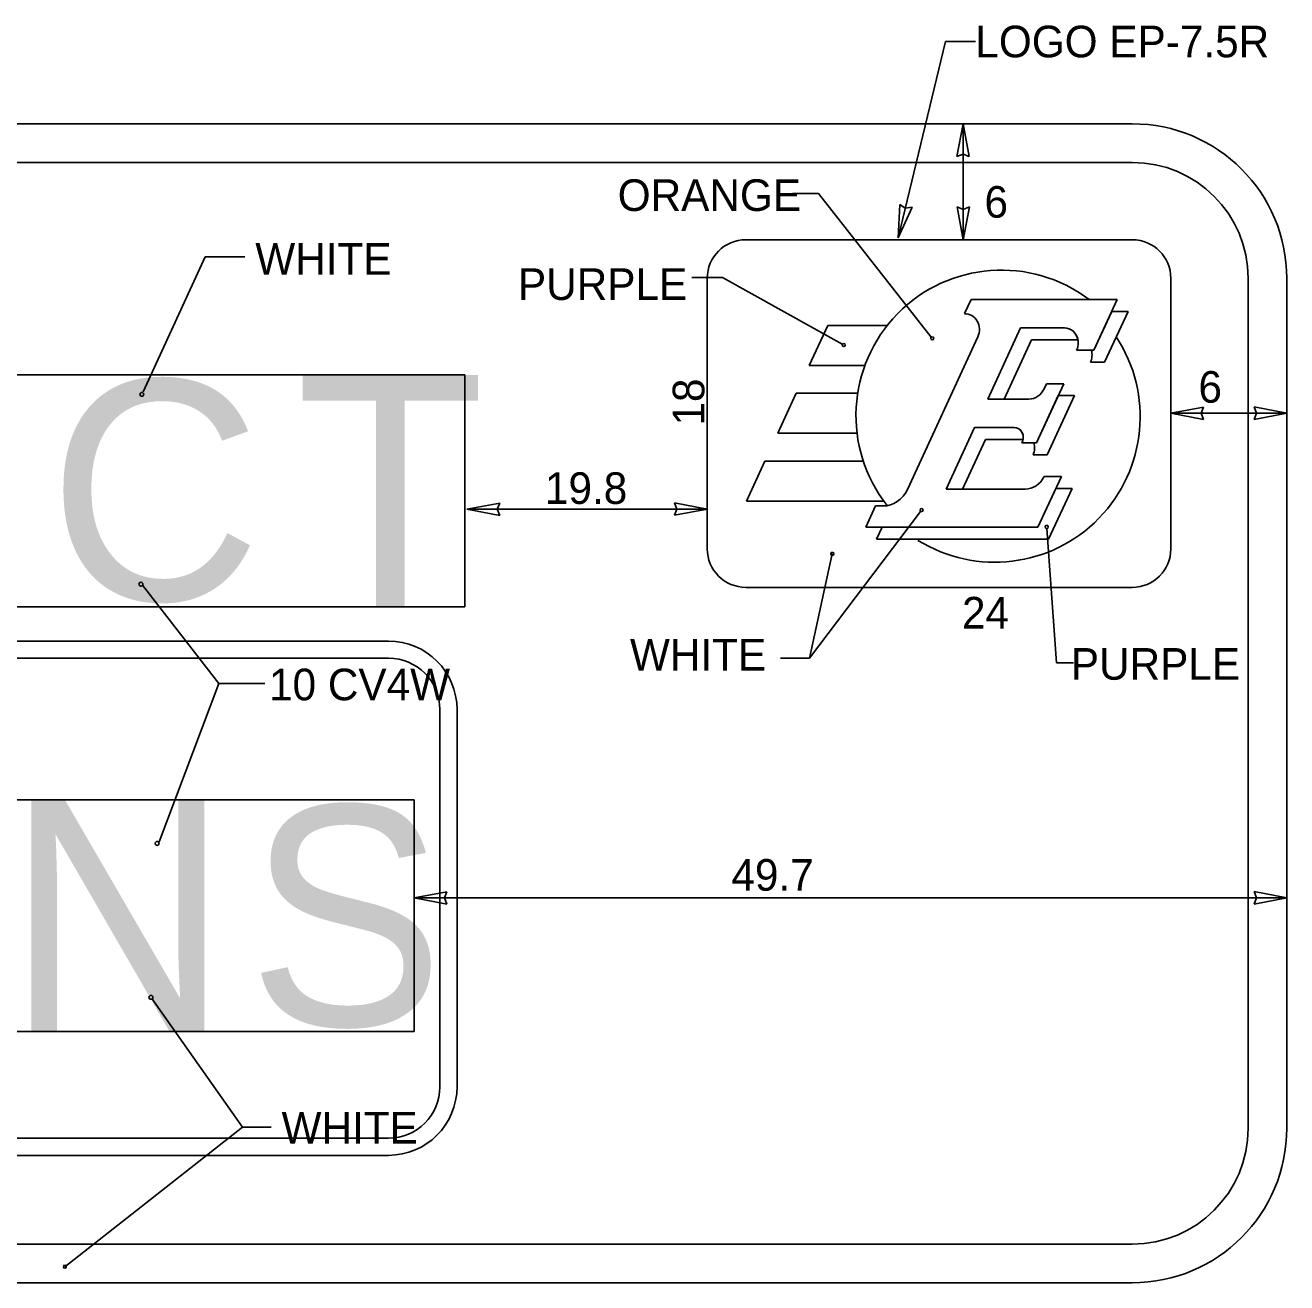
# Model space of a CAD drawing. Extents: x 319706 to 320346, y 1621790 to 1622121.
# Drawn here: x 319787.7 to 319843.5, y 1622064.8 to 1622120.5 of the extents above; entities that cross this region are included whole.
import ezdxf

# ---------------------------------------------------------------- set-up
doc = ezdxf.new("R2010")
doc.units = 0
for name, color, linetype in [('1', 7, 'Continuous'), ('52', 7, 'Continuous'), ('GSOutline', 7, 'Continuous'), ('SignPanel', 7, 'Continuous'), ('SOILS_SP83_SHP', 7, 'Continuous')]:
    doc.layers.add(name, color=color, linetype=linetype)

msp = doc.modelspace()

# ---------------------------------------------------------------- linework, layer by layer
at = {"layer": '1'}
for p, q in [((319826.341, 1622111.1), (319828.431, 1622119.783)), ((319828.431, 1622119.783), (319829.754, 1622119.783)), ((319829.217, 1622111.012), (319829.217, 1622116.142)), ((319821.667, 1622113.057), (319822.816, 1622113.057)), ((319822.816, 1622113.057), (319827.798, 1622106.695)), ((319795.671, 1622110.252), (319792.921, 1622104.281)), ((319797.422, 1622110.252), (319795.671, 1622110.252)), ((319817.21, 1622109.331), (319818.56, 1622109.331)), ((319818.56, 1622109.331), (319823.895, 1622106.373)), ((319838.407, 1622103.329), (319843.537, 1622103.329)), ((319822.411, 1622092.485), (319827.326, 1622098.98)), ((319833.339, 1622092.275), (319832.92, 1622098.223)), ((319822.411, 1622092.485), (319823.424, 1622097.107)), ((319796.271, 1622091.368), (319792.887, 1622095.721)), ((319821.127, 1622092.485), (319822.411, 1622092.485)), ((319834.105, 1622092.275), (319833.339, 1622092.275)), ((319796.271, 1622091.368), (319793.625, 1622084.362)), ((319798.305, 1622091.368), (319796.271, 1622091.368)), ((319804.916, 1622081.875), (319843.537, 1622081.875)), ((319797.321, 1622071.725), (319793.301, 1622077.427)), ((319797.321, 1622071.725), (319789.454, 1622065.552)), ((319798.58, 1622071.725), (319797.321, 1622071.725))]:
    msp.add_line(p, q, dxfattribs=at)
for centre, major_axis, ratio in [((319823.928, 1622106.348), (0, 0.0707), 0.906668), ((319827.845, 1622106.646), (0, 0.0707), 0.906668), ((319792.863, 1622104.164), (0.0872, 0), 0.980296), ((319827.373, 1622099.044), (0, 0.0707), 0.906668), ((319832.911, 1622098.299), (0, 0.0707), 0.906668), ((319823.423, 1622097.106), (0, 0.0707), 0.906668), ((319792.822, 1622095.763), (0.0872, 0), 0.980296), ((319793.54, 1622084.287), (0.0881, 0), 0.97059), ((319793.267, 1622077.473), (0.0881, 0), 0.97059), ((319789.453, 1622065.552), (0, 0.0707), 0.906668)]:
    msp.add_ellipse(centre, major_axis=major_axis, ratio=ratio, dxfattribs=at)
at = {"layer": '52'}
for p, q in [((319829.217, 1622116.142), (319828.937, 1622114.692)), ((319829.487, 1622114.692), (319829.217, 1622116.142)), ((319828.937, 1622114.692), (319829.217, 1622114.802)), ((319829.217, 1622114.802), (319829.487, 1622114.692)), ((319826.418, 1622112.573), (319826.341, 1622111.1)), ((319826.654, 1622112.403), (319826.418, 1622112.573)), ((319826.341, 1622111.1), (319826.952, 1622112.445)), ((319826.952, 1622112.445), (319826.654, 1622112.403)), ((319829.217, 1622112.352), (319828.947, 1622112.462)), ((319828.947, 1622112.462), (319829.217, 1622111.012)), ((319829.217, 1622111.012), (319829.497, 1622112.462)), ((319829.497, 1622112.462), (319829.217, 1622112.352)), ((319843.537, 1622103.329), (319842.087, 1622103.609)), ((319842.087, 1622103.609), (319842.197, 1622103.329)), ((319839.857, 1622103.599), (319838.407, 1622103.329)), ((319838.407, 1622103.329), (319839.857, 1622103.049)), ((319839.747, 1622103.329), (319839.857, 1622103.599)), ((319839.857, 1622103.049), (319839.747, 1622103.329)), ((319842.197, 1622103.329), (319842.087, 1622103.059)), ((319842.087, 1622103.059), (319843.537, 1622103.329)), ((319808.702, 1622099.355), (319807.252, 1622099.085)), ((319808.592, 1622099.085), (319808.702, 1622099.355)), ((319817.887, 1622099.085), (319816.437, 1622099.365)), ((319816.437, 1622099.365), (319816.547, 1622099.085)), ((319807.252, 1622099.085), (319808.702, 1622098.805)), ((319808.702, 1622098.805), (319808.592, 1622099.085)), ((319816.547, 1622099.085), (319816.437, 1622098.815)), ((319816.437, 1622098.815), (319817.887, 1622099.085)), ((319806.366, 1622082.145), (319804.916, 1622081.875)), ((319804.916, 1622081.875), (319806.366, 1622081.595)), ((319806.256, 1622081.875), (319806.366, 1622082.145)), ((319806.366, 1622081.595), (319806.256, 1622081.875)), ((319843.537, 1622081.875), (319842.087, 1622082.155)), ((319842.087, 1622082.155), (319842.197, 1622081.875)), ((319842.197, 1622081.875), (319842.087, 1622081.605)), ((319842.087, 1622081.605), (319843.537, 1622081.875))]:
    msp.add_line(p, q, dxfattribs=at)
at = {"layer": 'GSOutline'}
for p, q in [((319803.779, 1622093.246), (319755.212, 1622093.246)), ((319803.779, 1622092.488), (319755.212, 1622092.488)), ((319806.055, 1622073.516), (319806.055, 1622090.211)), ((319806.814, 1622073.516), (319806.814, 1622090.211)), ((319755.212, 1622071.24), (319803.779, 1622071.24)), ((319755.212, 1622070.481), (319803.779, 1622070.481))]:
    msp.add_line(p, q, dxfattribs=at)
for centre, radius, start, end in [((319803.779, 1622090.211), 3.035, 0, 90), ((319803.779, 1622090.211), 2.277, 0, 90), ((319803.779, 1622073.516), 3.035, 270, 0), ((319803.779, 1622073.516), 2.277, 270, 0)]:
    msp.add_arc(centre, radius, start, end, dxfattribs=at)
at = {"layer": 'SignPanel'}
for p, q in [((319727.257, 1622116.142), (319836.697, 1622116.142)), ((319727.257, 1622114.432), (319836.697, 1622114.432)), ((319819.597, 1622111.012), (319836.697, 1622111.012)), ((319817.887, 1622097.332), (319817.887, 1622109.302)), ((319838.407, 1622097.332), (319838.407, 1622109.302)), ((319841.827, 1622071.682), (319841.827, 1622109.302)), ((319843.537, 1622071.682), (319843.537, 1622109.302)), ((319829.565, 1622108.368), (319829.274, 1622107.738)), ((319829.565, 1622108.368), (319836.037, 1622108.368)), ((319836.037, 1622108.368), (319835, 1622106.123)), ((319835, 1622106.123), (319835.792, 1622107.837)), ((319836.511, 1622107.837), (319835.474, 1622105.592)), ((319836.511, 1622107.837), (319835.474, 1622105.592)), ((319835.792, 1622107.837), (319836.511, 1622107.837)), ((319835.792, 1622107.837), (319836.511, 1622107.837)), ((319823.219, 1622107.217), (319822.402, 1622105.449)), ((319825.858, 1622107.217), (319823.219, 1622107.217)), ((319831.757, 1622107.108), (319830.303, 1622103.959)), ((319831.757, 1622107.108), (319830.303, 1622103.959)), ((319833.699, 1622107.108), (319831.757, 1622107.108)), ((319833.699, 1622107.108), (319831.757, 1622107.108)), ((319826.746, 1622099.958), (319829.864, 1622106.709)), ((319832.232, 1622106.577), (319831.022, 1622103.959)), ((319831.022, 1622103.959), (319832.232, 1622106.577)), ((319834.294, 1622106.577), (319832.232, 1622106.577)), ((319832.232, 1622106.577), (319834.294, 1622106.577)), ((319835, 1622106.123), (319834.238, 1622106.123)), ((319834.886, 1622106.123), (319835, 1622106.123)), ((319824.868, 1622105.449), (319822.402, 1622105.449)), ((319834.849, 1622105.592), (319835.474, 1622105.592)), ((319835.474, 1622105.592), (319834.849, 1622105.592)), ((319821.83, 1622104.212), (319821.013, 1622102.444)), ((319824.548, 1622104.212), (319821.83, 1622104.212)), ((319833.667, 1622104.638), (319832.457, 1622102.018)), ((319832.905, 1622104.638), (319832.803, 1622104.416)), ((319832.905, 1622104.638), (319833.667, 1622104.638)), ((319830.303, 1622103.959), (319832.124, 1622103.959)), ((319830.303, 1622103.959), (319831.022, 1622103.959)), ((319832.457, 1622102.018), (319833.422, 1622104.108)), ((319834.141, 1622104.108), (319832.932, 1622101.488)), ((319834.141, 1622104.108), (319832.932, 1622101.488)), ((319833.422, 1622104.108), (319834.141, 1622104.108)), ((319833.422, 1622104.108), (319834.141, 1622104.108)), ((319829.72, 1622102.698), (319828.46, 1622099.969)), ((319829.72, 1622102.698), (319828.46, 1622099.969)), ((319831.476, 1622102.698), (319829.72, 1622102.698)), ((319831.476, 1622102.698), (319829.72, 1622102.698)), ((319824.52, 1622102.444), (319821.013, 1622102.444)), ((319830.197, 1622102.168), (319829.18, 1622099.969)), ((319829.18, 1622099.969), (319830.197, 1622102.168)), ((319831.869, 1622102.168), (319830.197, 1622102.168)), ((319830.197, 1622102.168), (319831.869, 1622102.168)), ((319831.814, 1622102.018), (319832.457, 1622102.018)), ((319832.344, 1622102.018), (319832.457, 1622102.018)), ((319832.932, 1622101.488), (319832.306, 1622101.488)), ((319832.932, 1622101.488), (319832.306, 1622101.488)), ((319820.441, 1622101.205), (319819.624, 1622099.438)), ((319824.797, 1622101.205), (319820.441, 1622101.205)), ((319833.561, 1622100.535), (319832.523, 1622098.289)), ((319832.798, 1622100.535), (319833.561, 1622100.535)), ((319828.46, 1622099.969), (319831.954, 1622099.969)), ((319828.46, 1622099.969), (319828.46, 1622099.969)), ((319828.46, 1622099.969), (319829.18, 1622099.969)), ((319832.523, 1622098.289), (319833.315, 1622100.004)), ((319834.035, 1622100.004), (319832.998, 1622097.758)), ((319834.035, 1622100.004), (319832.998, 1622097.758)), ((319833.315, 1622100.004), (319834.035, 1622100.004)), ((319833.315, 1622100.004), (319834.035, 1622100.004)), ((319819.624, 1622099.438), (319825.705, 1622099.438)), ((319824.909, 1622098.289), (319825.341, 1622099.225)), ((319825.341, 1622099.225), (319825.661, 1622099.225)), ((319807.252, 1622099.085), (319817.887, 1622099.085)), ((319832.523, 1622098.289), (319824.909, 1622098.289)), ((319825.383, 1622097.758), (319825.628, 1622098.289)), ((319825.383, 1622097.758), (319825.628, 1622098.289)), ((319825.628, 1622098.289), (319832.523, 1622098.289)), ((319832.998, 1622097.758), (319825.383, 1622097.758)), ((319832.998, 1622097.758), (319825.383, 1622097.758)), ((319819.597, 1622095.622), (319836.697, 1622095.622)), ((319726.616, 1622066.552), (319836.697, 1622066.552)), ((319727.257, 1622064.842), (319836.697, 1622064.842))]:
    msp.add_line(p, q, dxfattribs=at)
for centre, radius, start, end in [((319836.697, 1622109.301), 6.84, 0, 90), ((319836.697, 1622109.301), 5.13, 0, 90), ((319819.597, 1622109.301), 1.71, 90, 180), ((319836.697, 1622109.301), 1.71, 0, 90), ((319830.91, 1622103.226), 6.439, 52.9547, 218.1763), ((319830.61, 1622103.173), 6.439, 238.1578, 33.3171), ((319819.597, 1622097.331), 1.71, 180, 270), ((319836.697, 1622097.331), 1.71, 270, 360), ((319836.697, 1622071.681), 5.13, 270, 0), ((319836.697, 1622071.681), 6.84, 270, 0)]:
    msp.add_arc(centre, radius, start, end, dxfattribs=at)
for centre, major_axis, start_param, end_param in [((319829.292, 1622107.029), (0, 0.707), 4.241328, 6.314398), ((319833.698, 1622106.435), (0, 0.672), 4.227342, 6.283185), ((319833.698, 1622106.435), (0, 0.672), 4.924772, 6.283185), ((319834.309, 1622105.904), (0, 0.672), 4.227342, 5.041732), ((319834.309, 1622105.904), (0, 0.672), 4.227342, 5.041732), ((319832.124, 1622104.797), (0, 0.84), 3.141593, 4.241405), ((319831.475, 1622102.255), (0, 0.442), 4.144801, 6.283185), ((319831.475, 1622102.255), (0, 0.442), 4.511031, 6.283185), ((319831.767, 1622101.8), (0, 0.672), 4.227342, 5.041732), ((319831.767, 1622101.8), (0, 0.672), 4.227342, 5.041732), ((319831.954, 1622101.018), (0, 1.05), 3.141593, 4.232591), ((319825.66, 1622100.568), (0, 1.344), 3.141593, 4.241135)]:
    msp.add_ellipse(centre, major_axis=major_axis, ratio=0.906668, start_param=start_param, end_param=end_param, dxfattribs=at)
at = {"layer": 'SOILS_SP83_SHP'}
for p, q in [((319756.748, 1622105.027), (319807.16, 1622105.027)), ((319807.16, 1622094.767), (319807.16, 1622105.027)), ((319756.748, 1622094.767), (319807.16, 1622094.767)), ((319758.755, 1622086.218), (319804.916, 1622086.218)), ((319804.916, 1622075.958), (319804.916, 1622086.218)), ((319758.755, 1622075.958), (319804.916, 1622075.958))]:
    msp.add_line(p, q, dxfattribs=at)

# ---------------------------------------------------------------- texts
at = {"layer": '1'}
for s, p in [('LOGO EP-7.5R', (319829.754, 1622119.083)), ('ORANGE', (319813.926, 1622112.283)), ('6', (319830.158, 1622111.985)), ('WHITE', (319797.885, 1622109.461)), ('PURPLE', (319809.511, 1622108.344)), ('6', (319839.627, 1622103.795)), ('19.8', (319810.704, 1622099.315)), ('24', (319829.163, 1622093.799)), ('WHITE', (319814.467, 1622091.941)), ('PURPLE', (319833.98, 1622091.534)), ('10 CV4W', (319798.494, 1622090.624)), ('49.7', (319818.957, 1622082.195)), ('WHITE', (319799.047, 1622071.002))]:
    msp.add_text(s, height=1.4, dxfattribs=at).set_placement(p)
msp.add_text('18', height=1.4, rotation=90, dxfattribs=at).set_placement((319817.759, 1622102.784))
at = {"layer": 'SignPanel'}
for s, height, p in [('C', 9.747, (319788.732, 1622095.05)), ('T', 10.26, (319799.67, 1622094.765)), ('N', 10.26, (319786.844, 1622075.961)), ('S', 9.747, (319797.55, 1622076.218))]:
    msp.add_text(s, height=height, dxfattribs=at).set_placement(p)

doc.saveas('drawing.dxf')
